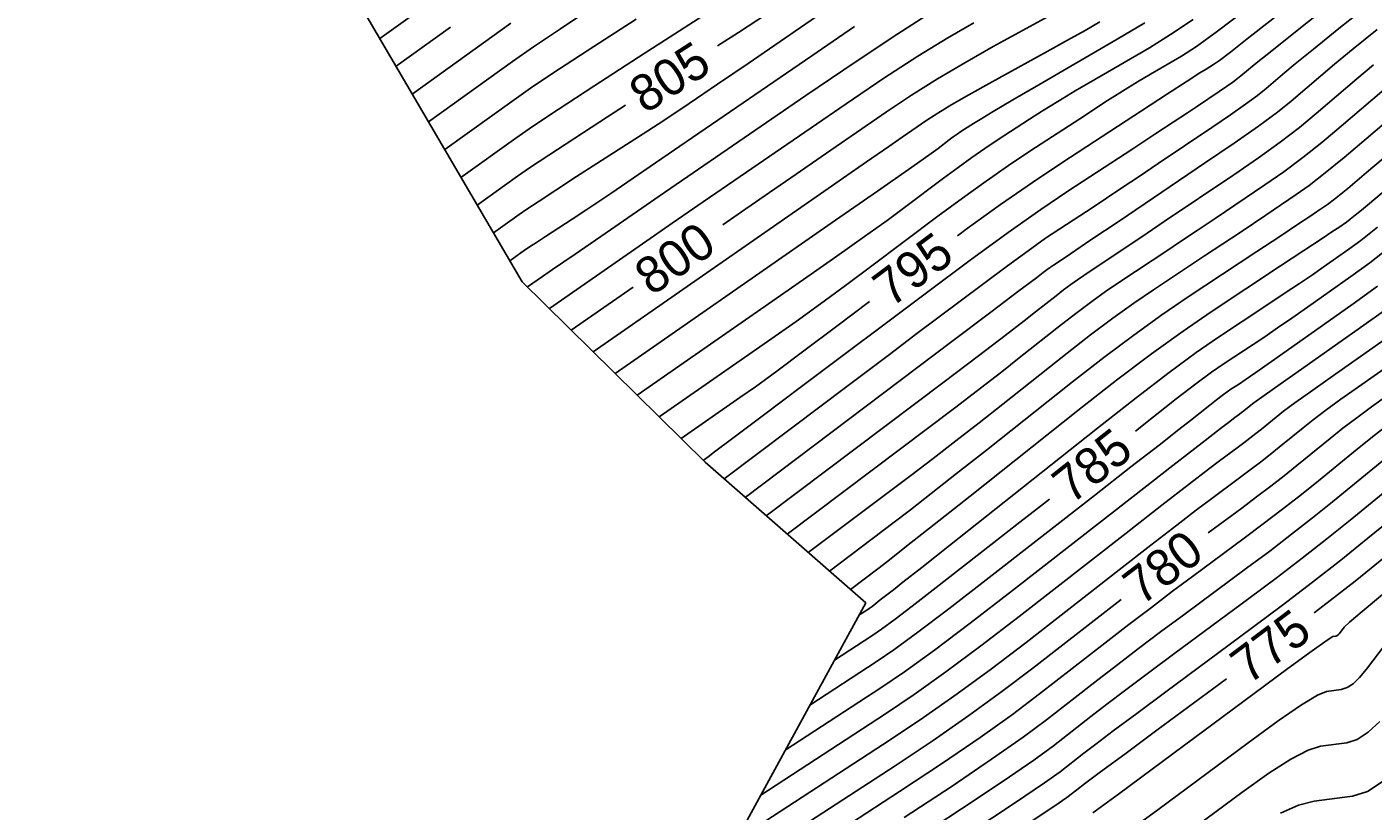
# Model space of a CAD drawing. Extents: x 2079879 to 2092887, y 778083 to 784051.
# Drawn here: x 2083804.7 to 2083907.9, y 780660.6 to 780720.7 of the extents above; entities that cross this region are included whole.
import ezdxf

# ---------------------------------------------------------------- set-up
doc = ezdxf.new("R2010")
doc.units = 0
for name, color, linetype in [('DT_X_Contour_Major', 7, 'Continuous'), ('DT_X_Contour_Minor', 7, 'Continuous'), ('DT_X_TIN_Hull', 7, 'Continuous')]:
    doc.layers.add(name, color=color, linetype=linetype)

msp = doc.modelspace()

# ---------------------------------------------------------------- linework, layer by layer
at = {"layer": 'DT_X_Contour_Major'}
for points in [[(2083908.78, 780728.2), (2083907, 780726.78), (2083905.13, 780725.29), (2083899.98, 780721.19), (2083898.26, 780719.82), (2083896.98, 780718.81), (2083896.12, 780718.16), (2083895.68, 780717.85), (2083895.1, 780717.51), (2083894.62, 780717.22), (2083893.64, 780716.58), (2083892.14, 780715.61), (2083890.14, 780714.31), (2083884.11, 780710.37), (2083881.79, 780708.82), (2083879.35, 780707.13), (2083876.79, 780705.28), (2083876.03, 780704.72)], [(2083861.47, 780721.76), (2083859.25, 780720.32), (2083857.65, 780719.28)], [(2083884.67, 780722.47), (2083878.78, 780719.23), (2083876.61, 780718), (2083874.52, 780716.76), (2083872.52, 780715.5), (2083870.6, 780714.22), (2083865.59, 780710.78), (2083863.66, 780709.45), (2083861.62, 780708.04), (2083859.47, 780706.55), (2083858.06, 780705.57)], [(2083837.17, 780720.72), (2083832.99, 780717.72)], [(2083911.32, 780718.11), (2083910.95, 780717.8), (2083909.44, 780716.52), (2083905.47, 780713.12), (2083903.98, 780711.89), (2083902.51, 780710.73), (2083901.06, 780709.64), (2083899.62, 780708.64), (2083895.79, 780706.06), (2083894.41, 780705.13), (2083893.15, 780704.29), (2083892.01, 780703.53), (2083890.98, 780702.84), (2083888.4, 780701.14), (2083887.4, 780700.45), (2083886.33, 780699.69), (2083885.21, 780698.85), (2083884.02, 780697.92), (2083880.78, 780695.35), (2083879.43, 780694.29), (2083877.8, 780693.03), (2083875.91, 780691.58), (2083873.74, 780689.94), (2083862.99, 780681.83)], [(2083850.59, 780714.73), (2083849.21, 780713.84), (2083846.69, 780712.21), (2083844.7, 780710.9), (2083843.23, 780709.93), (2083842.31, 780709.29), (2083839.22, 780707.07)], [(2083909.48, 780704.08), (2083907.65, 780702.66), (2083906.21, 780701.59), (2083902.88, 780699.25), (2083901.68, 780698.41), (2083900.59, 780697.66), (2083899.6, 780696.98), (2083898.71, 780696.39), (2083896.49, 780694.92), (2083895.53, 780694.26), (2083894.31, 780693.36), (2083892.82, 780692.22), (2083891.08, 780690.85), (2083889.68, 780689.74)], [(2083851.17, 780700.77), (2083846.43, 780697.48)], [(2083869.3, 780699.68), (2083866.78, 780697.78), (2083864.25, 780695.89), (2083862.18, 780694.35), (2083860.54, 780693.15), (2083859.35, 780692.31), (2083854.84, 780689.17)], [(2083908.97, 780692.45), (2083907.78, 780691.6), (2083906.65, 780690.77), (2083905.59, 780689.96), (2083904.61, 780689.17), (2083902.07, 780687.11), (2083901.09, 780686.32), (2083900.06, 780685.52), (2083898.98, 780684.69), (2083897.85, 780683.84), (2083895.26, 780681.93)], [(2083883.09, 780684.52), (2083882.4, 780683.98), (2083880.6, 780682.57), (2083878.84, 780681.19), (2083874.18, 780677.56), (2083872.57, 780676.32), (2083871.25, 780675.31), (2083870.21, 780674.55), (2083869.46, 780674.03), (2083866.6, 780672.17)], [(2083908.87, 780680.12), (2083906.53, 780678.24), (2083904.06, 780676.31), (2083903.39, 780675.8)], [(2083888.59, 780676.83), (2083887.89, 780676.29), (2083881.82, 780671.56), (2083879.45, 780669.76), (2083876.9, 780667.92), (2083874.17, 780666.02), (2083871.25, 780664.08), (2083857.19, 780654.91)], [(2083896.67, 780670.75), (2083891.33, 780666.8), (2083888.86, 780664.97), (2083887.01, 780663.6), (2083885.79, 780662.69), (2083885.2, 780662.23), (2083884.43, 780661.64), (2083883.51, 780661), (2083881.3, 780659.54), (2083877.81, 780657.25), (2083873.04, 780654.13), (2083847.78, 780637.66)]]:
    msp.add_lwpolyline(points, dxfattribs=at)
at = {"layer": 'DT_X_Contour_Minor'}
for points in [[(2083908.16, 780730.03), (2083900.65, 780724.04), (2083898.07, 780722.01), (2083895.97, 780720.41), (2083894.36, 780719.24), (2083893.22, 780718.5), (2083890.83, 780717.11), (2083889.84, 780716.52), (2083888.69, 780715.81), (2083887.35, 780714.96), (2083885.85, 780713.98), (2083881.6, 780711.21), (2083879.96, 780710.12), (2083878.24, 780708.92), (2083876.43, 780707.62), (2083874.54, 780706.22), (2083869.37, 780702.33), (2083867.45, 780700.9), (2083865.54, 780699.5), (2083863.66, 780698.15), (2083861.8, 780696.84), (2083853.16, 780690.83)], [(2083841.55, 780726.89), (2083831.74, 780719.85)], [(2083861.73, 780724.96), (2083851.59, 780718.42), (2083848.15, 780716.2), (2083845.43, 780714.42), (2083843.44, 780713.1), (2083842.18, 780712.22), (2083837.97, 780709.2)], [(2083905.15, 780722.91), (2083902.34, 780720.67), (2083900.27, 780719.02), (2083898.94, 780717.96), (2083898.35, 780717.48), (2083897.78, 780716.99), (2083897.51, 780716.78), (2083897.15, 780716.5), (2083896.68, 780716.17), (2083896.1, 780715.78), (2083894.45, 780714.67), (2083893.67, 780714.15), (2083892.58, 780713.43), (2083891.18, 780712.51), (2083889.48, 780711.39), (2083884.5, 780708.15), (2083882.43, 780706.75), (2083879.93, 780704.98), (2083877.01, 780702.86), (2083873.66, 780700.36), (2083864.18, 780693.23), (2083861.06, 780690.88), (2083858.81, 780689.19), (2083857.42, 780688.15), (2083856.91, 780687.77), (2083856.53, 780687.5)], [(2083907.81, 780722.61), (2083905.28, 780720.61), (2083903.33, 780719.04), (2083901.94, 780717.92), (2083901.13, 780717.24), (2083899.7, 780716.02), (2083899.04, 780715.49), (2083898.13, 780714.82), (2083896.97, 780714), (2083895.55, 780713.03), (2083891.44, 780710.26), (2083889.97, 780709.27), (2083888.65, 780708.39), (2083887.47, 780707.61), (2083886.44, 780706.93), (2083883.88, 780705.26), (2083882.79, 780704.53), (2083881.46, 780703.58), (2083879.88, 780702.43), (2083878.05, 780701.06), (2083872.83, 780697.14), (2083870.92, 780695.7), (2083869.09, 780694.32), (2083867.34, 780693.01), (2083865.69, 780691.76), (2083858.15, 780686.07)], [(2083848.09, 780722.25), (2083845.59, 780720.6), (2083843.53, 780719.21), (2083841.93, 780718.09), (2083835.48, 780713.46)], [(2083866.45, 780722.38), (2083859.99, 780717.94), (2083857.64, 780716.34), (2083855.46, 780714.87), (2083853.44, 780713.52), (2083851.58, 780712.31), (2083846.83, 780709.26), (2083845.23, 780708.21), (2083843.96, 780707.38), (2083843.02, 780706.77), (2083842.43, 780706.36), (2083840.47, 780704.94)], [(2083873.97, 780721.81), (2083871.46, 780720.21), (2083868.27, 780718.1), (2083864.4, 780715.47), (2083853.16, 780707.75), (2083849.44, 780705.19), (2083846.72, 780703.32), (2083844.98, 780702.13), (2083844.23, 780701.61), (2083843.06, 780700.8)], [(2083841.8, 780721.02), (2083834.23, 780715.59)], [(2083851.39, 780721.34), (2083848.16, 780719.25), (2083845.53, 780717.52), (2083843.49, 780716.16), (2083842.05, 780715.16), (2083836.73, 780711.33)], [(2083868.15, 780720.77), (2083864.86, 780718.53), (2083855.24, 780711.93), (2083851.99, 780709.7), (2083849.45, 780707.97), (2083847.62, 780706.73), (2083846.5, 780705.99), (2083844.46, 780704.67), (2083843.76, 780704.22), (2083843.22, 780703.87), (2083842.81, 780703.6), (2083842.56, 780703.42), (2083841.71, 780702.81)], [(2083877.29, 780721.06), (2083875.29, 780719.91), (2083872.99, 780718.49), (2083870.4, 780716.8), (2083867.5, 780714.84), (2083859.38, 780709.26), (2083856.55, 780707.32), (2083854.17, 780705.68), (2083852.22, 780704.34), (2083850.72, 780703.3), (2083844.75, 780699.14)], [(2083886.96, 780721.12), (2083885.83, 780720.47), (2083884.48, 780719.72), (2083882.91, 780718.86), (2083878.46, 780716.41), (2083876.91, 780715.54), (2083875.6, 780714.79), (2083874.53, 780714.14), (2083873.7, 780713.59), (2083871.8, 780712.29), (2083870.77, 780711.58), (2083869.07, 780710.4), (2083866.71, 780708.76), (2083863.7, 780706.67), (2083848.11, 780695.81)], [(2083890.4, 780721.06), (2083888.29, 780719.8), (2083882.29, 780716.3), (2083880.29, 780715.14), (2083878.78, 780714.25), (2083877.78, 780713.65), (2083877.27, 780713.34), (2083876.57, 780712.89), (2083876.3, 780712.71), (2083876.02, 780712.51), (2083875.72, 780712.3), (2083875.41, 780712.07), (2083874.57, 780711.43), (2083873.84, 780710.91), (2083872.28, 780709.81), (2083869.9, 780708.15), (2083866.69, 780705.91), (2083849.8, 780694.15)], [(2083894.1, 780721.31), (2083892.38, 780720.15), (2083890.76, 780719.15), (2083886.56, 780716.71), (2083885.07, 780715.83), (2083883.73, 780715.03), (2083882.56, 780714.31), (2083881.56, 780713.66), (2083879.08, 780712.05), (2083878.13, 780711.41), (2083877.13, 780710.72), (2083876.08, 780709.96), (2083874.97, 780709.14), (2083871.97, 780706.88), (2083870.64, 780705.9), (2083868.91, 780704.66), (2083866.78, 780703.15), (2083864.24, 780701.38), (2083851.48, 780692.49)], [(2083908.23, 780720.54), (2083906.39, 780719.06), (2083904.95, 780717.88), (2083903.9, 780717), (2083901.62, 780715.06), (2083900.57, 780714.21), (2083899.11, 780713.13), (2083897.25, 780711.82), (2083894.99, 780710.28), (2083888.43, 780705.85), (2083886.27, 780704.4), (2083884.71, 780703.35), (2083883.75, 780702.7), (2083883.4, 780702.46), (2083883.25, 780702.37), (2083883.19, 780702.33), (2083883.11, 780702.27), (2083883.02, 780702.21), (2083882.92, 780702.13), (2083882.62, 780701.9), (2083882.09, 780701.51), (2083880.75, 780700.49), (2083878.59, 780698.86), (2083875.6, 780696.61), (2083859.76, 780684.66)], [(2083907.95, 780717.84), (2083906.67, 780716.76), (2083903.54, 780714.09), (2083902.27, 780713.04), (2083900.79, 780711.91), (2083899.11, 780710.7), (2083897.22, 780709.4), (2083891.9, 780705.82), (2083890.1, 780704.6), (2083888.68, 780703.64), (2083887.64, 780702.95), (2083886.98, 780702.51), (2083885.72, 780701.68), (2083885.24, 780701.35), (2083884.72, 780700.98), (2083884.18, 780700.57), (2083883.61, 780700.12), (2083882.03, 780698.88), (2083881.15, 780698.19), (2083879.69, 780697.07), (2083877.64, 780695.52), (2083875.01, 780693.53), (2083861.38, 780683.24)], [(2083912.21, 780716.28), (2083907.39, 780712.15), (2083905.7, 780710.73), (2083904.24, 780709.54), (2083903.01, 780708.59), (2083902.02, 780707.88), (2083899.68, 780706.3), (2083898.73, 780705.67), (2083897.63, 780704.93), (2083896.39, 780704.1), (2083894.99, 780703.18), (2083891.07, 780700.59), (2083889.55, 780699.56), (2083887.94, 780698.4), (2083886.24, 780697.12), (2083884.44, 780695.72), (2083879.52, 780691.82), (2083877.7, 780690.38), (2083875.91, 780688.99), (2083874.17, 780687.65), (2083872.47, 780686.35), (2083864.6, 780680.42)], [(2083909.31, 780711.19), (2083907.41, 780709.57), (2083905.96, 780708.35), (2083904.96, 780707.53), (2083904.42, 780707.12), (2083903.57, 780706.55), (2083903.05, 780706.2), (2083902.11, 780705.58), (2083900.76, 780704.68), (2083899, 780703.52), (2083893.74, 780700.05), (2083891.71, 780698.66), (2083889.55, 780697.11), (2083887.27, 780695.4), (2083884.86, 780693.52), (2083878.27, 780688.29), (2083875.97, 780686.48), (2083874.03, 780684.95), (2083872.43, 780683.71), (2083871.19, 780682.76), (2083866.22, 780679.01)], [(2083909.43, 780708.7), (2083907.64, 780707.21), (2083907.03, 780706.7), (2083906.53, 780706.3), (2083906.14, 780705.99), (2083905.86, 780705.78), (2083905.27, 780705.37), (2083904.83, 780705.07), (2083903.94, 780704.47), (2083902.6, 780703.59), (2083900.82, 780702.41), (2083895.48, 780698.88), (2083893.34, 780697.42), (2083890.93, 780695.67), (2083888.24, 780693.64), (2083885.28, 780691.32), (2083877.01, 780684.76), (2083874.25, 780682.57), (2083872.14, 780680.91), (2083870.7, 780679.77), (2083869.92, 780679.17), (2083867.83, 780677.6)], [(2083908.25, 780705.39), (2083906.96, 780704.37), (2083906.04, 780703.69), (2083904.07, 780702.31), (2083903.25, 780701.74), (2083902.26, 780701.07), (2083901.1, 780700.29), (2083899.77, 780699.4), (2083895.99, 780696.9), (2083894.35, 780695.77), (2083892.27, 780694.23), (2083889.74, 780692.3), (2083886.77, 780689.97), (2083878.27, 780683.23), (2083875.43, 780680.98), (2083873.3, 780679.28), (2083871.86, 780678.15), (2083871.13, 780677.58), (2083870.12, 780676.79), (2083869.77, 780676.52), (2083869.49, 780676.3), (2083869.26, 780676.14), (2083869.1, 780676.02), (2083868.48, 780675.62)], [(2083908.24, 780700.85), (2083906.38, 780699.5), (2083901.68, 780696.19), (2083900.11, 780695.09), (2083898.91, 780694.25), (2083898.09, 780693.68), (2083897.66, 780693.38), (2083897, 780692.95), (2083896.71, 780692.75), (2083896.34, 780692.48), (2083895.9, 780692.14), (2083895.38, 780691.73), (2083893.9, 780690.55), (2083893.02, 780689.86), (2083891.5, 780688.67), (2083889.34, 780686.99), (2083886.55, 780684.81), (2083878.23, 780678.33), (2083875.37, 780676.11), (2083873.01, 780674.33), (2083871.16, 780672.97), (2083869.81, 780672.04), (2083864.71, 780668.72)], [(2083909.31, 780699.38), (2083907.39, 780697.99), (2083902.43, 780694.5), (2083900.78, 780693.34), (2083899.56, 780692.48), (2083898.77, 780691.91), (2083898.4, 780691.63), (2083897.99, 780691.3), (2083897.83, 780691.18), (2083897.67, 780691.05), (2083897.49, 780690.91), (2083897.31, 780690.78), (2083896.81, 780690.41), (2083896.22, 780689.95), (2083894.8, 780688.85), (2083892.56, 780687.11), (2083889.5, 780684.72), (2083880.25, 780677.51), (2083877.02, 780675.02), (2083874.27, 780672.94), (2083871.98, 780671.29), (2083870.17, 780670.05), (2083862.83, 780665.27)], [(2083909.01, 780696.92), (2083904.61, 780693.82), (2083903.11, 780692.76), (2083901.92, 780691.91), (2083901.04, 780691.26), (2083900.47, 780690.81), (2083899.35, 780689.9), (2083898.92, 780689.56), (2083898.47, 780689.2), (2083897.99, 780688.84), (2083897.49, 780688.47), (2083896.13, 780687.46), (2083895.3, 780686.83), (2083893.83, 780685.69), (2083891.72, 780684.05), (2083888.97, 780681.91), (2083880.78, 780675.53), (2083877.83, 780673.27), (2083875.15, 780671.27), (2083872.71, 780669.53), (2083870.53, 780668.06), (2083860.95, 780661.82)], [(2083910.64, 780695.84), (2083906.79, 780693.14), (2083905.44, 780692.18), (2083904.29, 780691.34), (2083903.32, 780690.61), (2083902.54, 780689.99), (2083900.71, 780688.51), (2083900.01, 780687.94), (2083899.27, 780687.36), (2083898.49, 780686.77), (2083897.67, 780686.15), (2083895.44, 780684.5), (2083894.38, 780683.7), (2083892.85, 780682.54), (2083890.87, 780681), (2083888.43, 780679.1), (2083881.3, 780673.54), (2083878.64, 780671.51), (2083876.02, 780669.59), (2083873.44, 780667.78), (2083870.89, 780666.07), (2083859.07, 780658.36)], [(2083909.01, 780690.2), (2083907.87, 780689.31), (2083906.68, 780688.35), (2083903.43, 780685.71), (2083902.18, 780684.71), (2083900.86, 780683.68), (2083899.48, 780682.62), (2083898.03, 780681.53), (2083894.07, 780678.6), (2083892.54, 780677.46), (2083890.91, 780676.22), (2083889.18, 780674.9), (2083887.35, 780673.48), (2083882.34, 780669.58), (2083880.27, 780668.01), (2083877.78, 780666.24), (2083874.9, 780664.27), (2083871.6, 780662.09), (2083855.3, 780651.46)], [(2083908.74, 780687.53), (2083904.79, 780684.31), (2083903.27, 780683.09), (2083901.66, 780681.83), (2083899.98, 780680.54), (2083898.21, 780679.22), (2083893.39, 780675.65), (2083891.62, 780674.34), (2083889.93, 780673.07), (2083888.33, 780671.84), (2083886.81, 780670.67), (2083882.87, 780667.59), (2083881.08, 780666.26), (2083878.66, 780664.57), (2083875.62, 780662.52), (2083871.96, 780660.1)], [(2083910.81, 780686.71), (2083906.15, 780682.91), (2083904.35, 780681.47), (2083902.46, 780679.99), (2083900.47, 780678.47), (2083898.39, 780676.91), (2083892.7, 780672.7), (2083890.7, 780671.21), (2083888.96, 780669.91), (2083887.49, 780668.79), (2083886.27, 780667.86), (2083883.39, 780665.61), (2083881.89, 780664.51), (2083879.54, 780662.89), (2083876.35, 780660.76), (2083872.32, 780658.11)], [(2083912.88, 780685.89), (2083907.51, 780681.52), (2083905.44, 780679.85), (2083903.26, 780678.15), (2083900.97, 780676.4), (2083898.57, 780674.6), (2083892.01, 780669.75), (2083889.78, 780668.09), (2083887.99, 780666.75), (2083886.64, 780665.74), (2083885.73, 780665.04), (2083883.91, 780663.62), (2083882.7, 780662.76), (2083880.42, 780661.22), (2083877.08, 780659.01)], [(2083908.63, 780677.21), (2083907.08, 780675.91), (2083906.1, 780675.08), (2083905.7, 780674.7), (2083905.42, 780674.33), (2083905.31, 780674.2), (2083905.22, 780674.11), (2083905.12, 780674.05), (2083905.04, 780674.02), (2083904.82, 780673.99), (2083904.38, 780673.71), (2083903.23, 780672.89), (2083901.36, 780671.53), (2083898.79, 780669.62), (2083890.98, 780663.82), (2083888.38, 780661.9), (2083886.42, 780660.46)], [(2083908.85, 780673.39), (2083907.4, 780671.48), (2083906.87, 780670.84), (2083906.37, 780670.37), (2083905.91, 780670.07), (2083905.47, 780669.93), (2083904.34, 780669.78), (2083903.65, 780669.49), (2083902.42, 780668.74), (2083900.64, 780667.52), (2083898.32, 780665.83), (2083891.41, 780660.7), (2083888.96, 780658.91)], [(2083908.43, 780667.48), (2083907.53, 780666.64), (2083906.69, 780666.09), (2083905.9, 780665.84), (2083903.87, 780665.57), (2083902.93, 780665.28), (2083901.61, 780664.59), (2083899.92, 780663.51), (2083897.85, 780662.03), (2083891.85, 780657.57)], [(2083908.69, 780662.9), (2083907.47, 780662.11), (2083906.33, 780661.75), (2083903.4, 780661.36), (2083902.2, 780661.06), (2083900.8, 780660.44)]]:
    msp.add_lwpolyline(points, dxfattribs=at)
at = {"layer": 'DT_X_TIN_Hull'}
msp.add_lwpolyline([(2083782.89, 780770.26), (2083804.98, 780759.65), (2083810.01, 780751.68), (2083817.96, 780743.39), (2083842.66, 780701.2), (2083856.68, 780687.35), (2083869, 780676.57), (2083846.43, 780635.19)], dxfattribs=at)

# ---------------------------------------------------------------- texts
at = {"layer": 'DT_X_Contour_Major'}
for s, rotation, p in [('805', 32.8189, (2083852.09, 780714.03)), ('800', 34.8401, (2083852.59, 780700.06)), ('795', 36.8382, (2083870.95, 780699.17)), ('785', 38.3752, (2083884.77, 780684.07)), ('780', 37.3548, (2083890.15, 780676.3)), ('775', 36.8883, (2083898.37, 780670.25))]:
    msp.add_text(s, height=2.8, rotation=rotation, dxfattribs=at).set_placement(p)

doc.saveas('drawing.dxf')
